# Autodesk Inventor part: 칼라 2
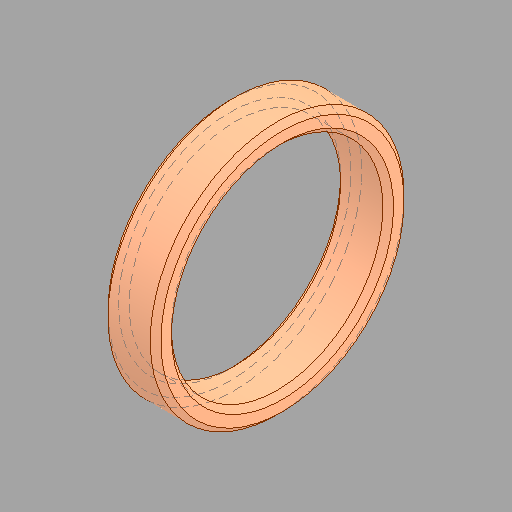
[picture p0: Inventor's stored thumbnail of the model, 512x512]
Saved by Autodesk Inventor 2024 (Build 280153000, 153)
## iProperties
Created: 2025-11
Part Number: 칼라 2
Material: 강철, 연강
Document SubType Name: Modeling
Designer: Edu09
Density: 7.85 g/cm^3
Appearance: 기본값
Author: jhkim
Sending System: Autodesk Inventor 2026
Preprocessor: ST-DEVELOPER v20.1
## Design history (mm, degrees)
feature "솔리드1"
node "솔리드2"
